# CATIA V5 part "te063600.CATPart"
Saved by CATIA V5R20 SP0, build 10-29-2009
Part number: 1
Definition: NONE
Nomenclature: 1
Source: Unknown
Description: PART-1-DESC
Bounding box of the stored display mesh (mm): x 0 to 600, y -3 to 3, z -2.853 to 2.853
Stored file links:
  C:\Users\Utente\Desktop\IO LAVORO\3D X SITO CF\CUMSA\3D files TE\te063600.CATPart
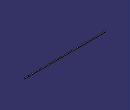
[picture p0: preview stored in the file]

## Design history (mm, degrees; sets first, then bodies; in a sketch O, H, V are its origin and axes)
Body1 "1" (main body)
  Solid1: solid without history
